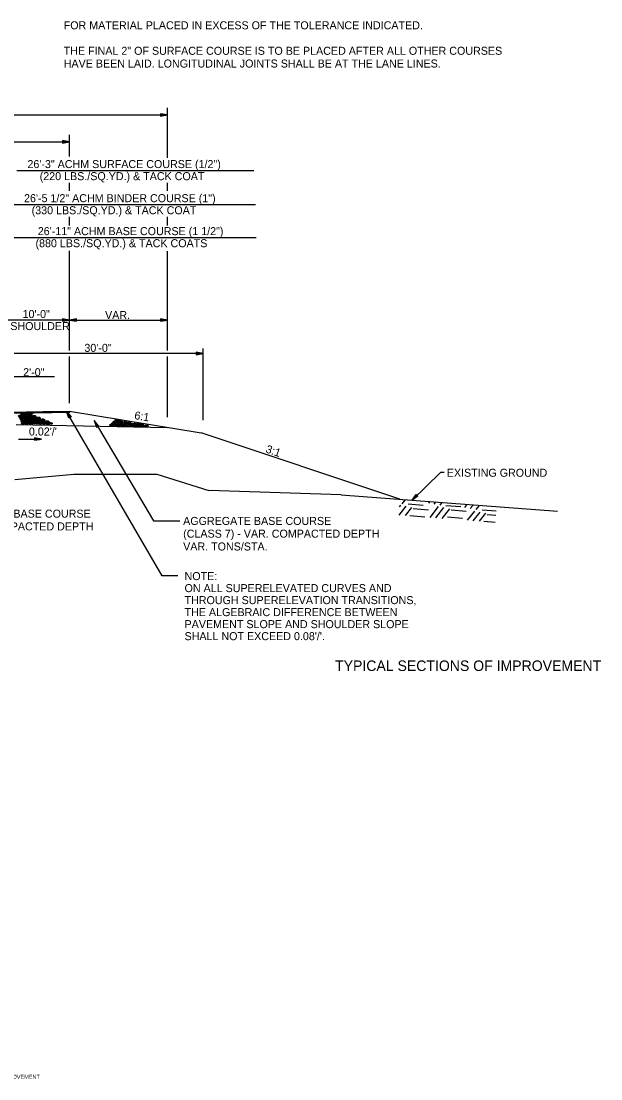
# Model space of a CAD drawing. Extents: x 1734743 to 1735935, y 759845 to 763831.
# Drawn here: x 1735827.7 to 1735914.7, y 762764.7 to 762923.3 of the extents above; entities that cross this region are included whole.
import ezdxf

# ---------------------------------------------------------------- set-up
doc = ezdxf.new("R2010")
doc.units = 0
for name, color, linetype in [('1', 7, 'Continuous'), ('10', 7, 'Continuous'), ('11', 7, 'Continuous'), ('19', 7, 'Continuous'), ('8', 7, 'Continuous'), ('9', 7, 'Continuous'), ('G-ANNO-TEXT', 7, 'Continuous'), ('Level 1', 7, 'Continuous'), ('R_Prop Surface', 7, 'Continuous')]:
    doc.layers.add(name, color=color, linetype=linetype)

# ---------------------------------------------------------------- blocks, each defined once
blk = doc.blocks.new('TM')
at = {"layer": '8'}
for p, q in [((-120.309, 21.181), (-119.787, -20.829)), ((0, 0), (-120.309, 21.181)), ((-31.382, 2.945), (-120.176, 10.512)), ((-119.787, -20.829), (0, 0)), ((-119.911, -10.826), (-31.307, -3.057))]:
    blk.add_line(p, q, dxfattribs=at)
blk = doc.blocks.new('ROCKS')
at = {"layer": '1'}
blk.add_spline([(0.013, 0.06), (0.053, 0.053), (0.107, 0.033), (0.133, 0.013), (0.133, -0.007), (0.12, -0.033), (0.107, -0.04), (0.073, -0.053), (0.033, -0.067), (0.013, -0.067), (-0.02, -0.06), (-0.06, -0.053), (-0.087, -0.047), (-0.113, -0.02), (-0.113, -0.007), (-0.107, 0.02), (-0.087, 0.033), (-0.067, 0.047), (-0.033, 0.053), (-0.02, 0.06), (0.013, 0.06)], degree=3, dxfattribs=at)

msp = doc.modelspace()

# ---------------------------------------------------------------- linework, layer by layer
at = {"layer": '11'}
for p, q in [((1735826.79, 762854.56), (1735835.65, 762855.39)), ((1735835.65, 762855.39), (1735848.06, 762855.39)), ((1735848.06, 762855.39), (1735855.89, 762852.91)), ((1735875.71, 762852.28), (1735855.89, 762852.91))]:
    msp.add_line(p, q, dxfattribs=at)
msp.add_lwpolyline([(1735875.71, 762852.28), (1735908.15, 762849.8)], dxfattribs=at)
at = {"layer": '19'}
for p, q in [((1735782.43, 762909.21), (1735849.62, 762909.21)), ((1735848.61, 762909.39), (1735848.61, 762909.03)), ((1735849.66, 762909.21), (1735848.61, 762909.39)), ((1735849.38, 762909.24), (1735848.61, 762909.3)), ((1735848.61, 762909.03), (1735849.66, 762909.21)), ((1735848.61, 762909.11), (1735849.38, 762909.18)), ((1735849.66, 762902.77), (1735849.66, 762910.26)), ((1735796.97, 762905.17), (1735834.97, 762905.17)), ((1735833.92, 762905.36), (1735833.92, 762904.99)), ((1735834.97, 762905.17), (1735833.92, 762905.36)), ((1735834.69, 762905.2), (1735833.92, 762905.26)), ((1735833.92, 762904.99), (1735834.97, 762905.17)), ((1735833.92, 762905.08), (1735834.69, 762905.15)), ((1735827.1, 762900.88), (1735862.63, 762900.88)), ((1735825.2, 762895.78), (1735862.86, 762895.78)), ((1735825.1, 762890.84), (1735862.96, 762890.84)), ((1735849.66, 762873.88), (1735849.66, 762888.81)), ((1735833.92, 762878.65), (1735833.92, 762878.28)), ((1735834.97, 762878.47), (1735833.92, 762878.65)), ((1735834.69, 762878.49), (1735833.92, 762878.56)), ((1735833.92, 762878.28), (1735834.97, 762878.47)), ((1735833.92, 762878.37), (1735834.69, 762878.44)), ((1735836.02, 762878.65), (1735834.97, 762878.47)), ((1735834.97, 762878.47), (1735836.02, 762878.28)), ((1735836.02, 762878.56), (1735835.25, 762878.49)), ((1735835.25, 762878.44), (1735836.02, 762878.37)), ((1735836.02, 762878.28), (1735836.02, 762878.65)), ((1735848.61, 762878.65), (1735848.61, 762878.28)), ((1735849.66, 762878.47), (1735848.61, 762878.65)), ((1735849.38, 762878.49), (1735848.61, 762878.56)), ((1735848.61, 762878.28), (1735849.66, 762878.47)), ((1735848.61, 762878.37), (1735849.38, 762878.44)), ((1735849.66, 762863.91), (1735849.66, 762873)), ((1735853.96, 762873.63), (1735853.96, 762873.26)), ((1735855.01, 762873.45), (1735853.96, 762873.63)), ((1735854.73, 762873.47), (1735853.96, 762873.53)), ((1735853.96, 762873.26), (1735855.01, 762873.45)), ((1735853.96, 762873.35), (1735854.73, 762873.42)), ((1735832.72, 762869.94), (1735824.97, 762869.94)), ((1735827, 762864.67), (1735834.97, 762864.83)), ((1735834.9, 762863.77), (1735834.53, 762864.77)), ((1735834.53, 762864.77), (1735835.22, 762863.95)), ((1735834.97, 762864.83), (1735854.71, 762861.54)), ((1735826.96, 762864.5), (1735835.05, 762864.66)), ((1735834.97, 762863.81), (1735834.64, 762864.51)), ((1735834.69, 762864.54), (1735835.13, 762863.91)), ((1735835.22, 762863.95), (1735834.9, 762863.77)), ((1735838.66, 762863.41), (1735847.59, 762848.36)), ((1735839.35, 762862.6), (1735838.66, 762863.41)), ((1735838.66, 762863.41), (1735839.04, 762862.42)), ((1735839.28, 762862.56), (1735838.83, 762863.19)), ((1735826.96, 762862.83), (1735849.66, 762862.38)), ((1735838.79, 762863.16), (1735839.12, 762862.47)), ((1735839.04, 762862.42), (1735839.35, 762862.6)), ((1735827.34, 762860.61), (1735830.76, 762860.61)), ((1735884.5, 762851.61), (1735854.71, 762861.54)), ((1735886.35, 762851.46), (1735886.98, 762852.33)), ((1735886.54, 762851.67), (1735887.04, 762852.26)), ((1735887.17, 762852.13), (1735886.57, 762851.64)), ((1735886.98, 762852.33), (1735887.23, 762852.07)), ((1735884.41, 762849.24), (1735885.44, 762850.55)), ((1735884.48, 762850.48), (1735884.66, 762850.7)), ((1735884.86, 762850.93), (1735885.3, 762851.48)), ((1735885.75, 762850.9), (1735888, 762850.7)), ((1735887.23, 762852.07), (1735886.35, 762851.46)), ((1735888.87, 762851.04), (1735888.98, 762851.19)), ((1735889.05, 762848.88), (1735890.33, 762850.5)), ((1735889.66, 762850.89), (1735889.84, 762851.12)), ((1735890.54, 762850.73), (1735890.79, 762851.05)), ((1735891.43, 762850.69), (1735893.68, 762850.5)), ((1735894.28, 762850.38), (1735894.58, 762850.75)), ((1735895.07, 762850.22), (1735895.44, 762850.69)), ((1735895.95, 762850.06), (1735896.39, 762850.61)), ((1735885.36, 762849.17), (1735886.32, 762850.39)), ((1735886.01, 762849.16), (1735888.26, 762848.97)), ((1735886.53, 762850.2), (1735888.79, 762850.01)), ((1735889.9, 762848.82), (1735891.12, 762850.35)), ((1735890.85, 762848.74), (1735892, 762850.18)), ((1735891.68, 762848.96), (1735893.93, 762848.77)), ((1735892.21, 762850), (1735894.46, 762849.81)), ((1735894.64, 762848.45), (1735895.75, 762849.84)), ((1735895.5, 762848.38), (1735896.54, 762849.68)), ((1735896.45, 762848.31), (1735897.42, 762849.52)), ((1735896.84, 762850.03), (1735898.94, 762849.85)), ((1735897.62, 762849.34), (1735898.89, 762849.23)), ((1735847.59, 762848.36), (1735851.5, 762848.36)), ((1735897.1, 762848.3), (1735898.81, 762848.15))]:
    msp.add_line(p, q, dxfattribs=at)
for points in [[(1735835.05, 762864.66), (1735827.05, 762864.5), (1735804.98, 762864.06), (1735800.88, 762863.98), (1735800.88, 762863.98), (1735796.88, 762863.9), (1735796.97, 762864.07), (1735796.97, 762864.07), (1735803.43, 762864.19), (1735830.97, 762864.75), (1735834.97, 762864.83), (1735834.97, 762864.83), (1735835.05, 762864.66), (1735835.05, 762864.66), (1735835.05, 762864.66)], [(1735891.18, 762855.64), (1735890.61, 762855.64), (1735886.35, 762851.46)]]:
    msp.add_lwpolyline(points, dxfattribs=at)
at = {"layer": '9'}
for p, q in [((1735834.97, 762902.98), (1735834.97, 762906.21)), ((1735834.97, 762897.82), (1735834.97, 762899.05)), ((1735849.66, 762897.82), (1735849.66, 762899.05)), ((1735834.97, 762892.62), (1735834.97, 762893.95)), ((1735849.66, 762892.62), (1735849.66, 762893.95)), ((1735834.97, 762879.38), (1735834.97, 762888.83)), ((1735834.97, 762873.88), (1735834.97, 762879.38)), ((1735834.97, 762878.47), (1735824.97, 762878.47)), ((1735834.97, 762878.47), (1735849.66, 762878.47)), ((1735855.01, 762873.45), (1735824.97, 762873.45)), ((1735834.97, 762867.93), (1735834.97, 762873)), ((1735855.01, 762863.45), (1735855.01, 762874.22)), ((1735834.97, 762866), (1735834.97, 762867.93)), ((1735848.85, 762840.14), (1735834.53, 762864.77))]:
    msp.add_line(p, q, dxfattribs=at)
msp.add_lwpolyline([(1735851.21, 762840.14), (1735848.85, 762840.14)], dxfattribs=at)
at = {"layer": 'R_Prop Surface'}
msp.add_line((1735834.97, 762864.83), (1735835.05, 762864.66), dxfattribs=at)

# ---------------------------------------------------------------- block references
at = {"layer": '19', "xscale": 0.008761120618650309, "yscale": 0.008761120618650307, "rotation": -0.7994241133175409}
msp.add_blockref('TM', (1735830.76, 762860.61), dxfattribs=at)
at = {"layer": 'Level 1'}
for p, xscale, yscale, rotation in [((1735827.6, 762864.07), 2.0116542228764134, -2.011654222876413, 177.9586193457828), ((1735827.75, 762863.81), 2.0116542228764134, -2.011654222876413, 177.9586193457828), ((1735827.89, 762863.56), 2.0116542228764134, -2.011654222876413, 177.9586193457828), ((1735828.01, 762864.35), 2.0116542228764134, -2.011654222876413, 177.9586193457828), ((1735828.02, 762863.29), 2.0116542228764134, -2.011654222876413, 177.9586193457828), ((1735828.13, 762864.08), 2.0116542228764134, -2.011654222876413, 177.9586193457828), ((1735828.29, 762863.82), 2.0116542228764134, -2.011654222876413, 177.9586193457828), ((1735828.44, 762863.55), 2.0116542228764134, -2.011654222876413, 177.9586193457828), ((1735828.56, 762863.29), 2.0116542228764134, -2.011654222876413, 177.9586193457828), ((1735828.59, 762864.38), 2.011654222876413, -2.0116542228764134, 177.95871721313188), ((1735828.67, 762864.12), 2.011654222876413, -2.0116542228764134, 177.95871721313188), ((1735828.82, 762863.85), 2.0116542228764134, -2.011654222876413, 177.9586193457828), ((1735828.96, 762863.59), 2.0116542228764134, -2.011654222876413, 177.9586193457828), ((1735829.09, 762863.31), 2.0116542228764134, -2.011654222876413, 177.9586193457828), ((1735829.09, 762863.04), 2.0116542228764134, -2.011654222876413, 177.9586193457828), ((1735829.11, 762864.34), 2.011654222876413, -2.0116542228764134, 177.95871721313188), ((1735829.2, 762864.07), 2.011654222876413, -2.0116542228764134, 177.95871721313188), ((1735829.33, 762863.81), 2.011654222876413, -2.0116542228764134, 177.95871721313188), ((1735829.46, 762863.56), 2.011654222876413, -2.0116542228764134, 177.95871721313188), ((1735829.58, 762863.3), 2.011654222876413, -2.0116542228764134, 177.95871721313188), ((1735829.7, 762864.05), 2.011654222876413, -2.0116542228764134, 177.95871721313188), ((1735829.84, 762863.8), 2.011654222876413, -2.0116542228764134, 177.95871721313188), ((1735829.97, 762863.55), 2.011654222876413, -2.0116542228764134, 177.95871721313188), ((1735830.09, 762863.3), 2.011654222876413, -2.0116542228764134, 177.95871721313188), ((1735830.35, 762863.8), 2.011654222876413, -2.0116542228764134, 177.95871721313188), ((1735830.49, 762863.54), 2.011654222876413, -2.0116542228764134, 177.95871721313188), ((1735830.62, 762863.27), 2.011654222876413, -2.0116542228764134, 177.95871721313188), ((1735831, 762863.52), 2.011654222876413, -2.0116542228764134, 177.95871721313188), ((1735831.13, 762863.27), 2.011654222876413, -2.0116542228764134, 177.95871721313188), ((1735831.66, 762863.25), 2.011654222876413, -2.0116542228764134, 177.95871721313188), ((1735841.78, 762863.21), 2.011654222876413, -2.011654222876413, 178.17361855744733), ((1735842.09, 762863.46), 2.011654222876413, -2.011654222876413, 178.17361855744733), ((1735842.29, 762863.2), 2.011654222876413, -2.011654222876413, 178.17361855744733), ((1735842.6, 762863.4), 2.011654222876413, -2.011654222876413, 178.17361855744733), ((1735842.8, 762863.16), 2.011654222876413, -2.011654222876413, 178.17361855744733), ((1735843.33, 762863.13), 2.011654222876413, -2.011654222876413, 178.17361855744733), ((1735843.89, 762863.09), 2.011654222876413, -2.011654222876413, 178.17361855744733), ((1735828.02, 762863), 2.0116542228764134, -2.011654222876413, 177.9586193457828), ((1735828.56, 762863.02), 2.0116542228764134, -2.011654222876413, 177.9586193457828), ((1735829.58, 762863.02), 2.011654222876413, -2.0116542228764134, 177.95871721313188), ((1735830.11, 762863.02), 2.011654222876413, -2.0116542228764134, 177.95871721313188), ((1735830.62, 762863), 2.011654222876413, -2.0116542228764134, 177.95871721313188), ((1735831.13, 762862.99), 2.011654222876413, -2.0116542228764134, 177.95871721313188), ((1735831.66, 762862.98), 2.011654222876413, -2.0116542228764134, 177.95871721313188), ((1735832.17, 762862.98), 2.011654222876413, -2.0116542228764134, 177.95871721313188), ((1735841.29, 762862.72), 2.011654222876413, -2.011654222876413, 178.17361855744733), ((1735841.56, 762862.96), 2.011654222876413, -2.011654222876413, 178.17361855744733), ((1735841.82, 762862.72), 2.011654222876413, -2.011654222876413, 178.17361855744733), ((1735842.06, 762862.97), 2.011654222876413, -2.011654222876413, 178.17361855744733), ((1735842.34, 762862.74), 2.011654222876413, -2.011654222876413, 178.17361855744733), ((1735842.59, 762862.95), 2.011654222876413, -2.011654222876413, 178.17361855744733), ((1735842.86, 762862.71), 2.011654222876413, -2.011654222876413, 178.17361855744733), ((1735843.11, 762862.92), 2.011654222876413, -2.011654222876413, 178.17361855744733), ((1735843.42, 762862.67), 2.011654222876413, -2.011654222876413, 178.17361855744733), ((1735843.67, 762862.87), 2.011654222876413, -2.011654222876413, 178.17361855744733), ((1735844.02, 762862.67), 2.011654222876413, -2.011654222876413, 178.17361855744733), ((1735844.28, 762862.87), 2.011654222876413, -2.011654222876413, 178.17361855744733), ((1735844.51, 762862.65), 2.011654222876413, -2.011654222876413, 178.17361855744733), ((1735844.77, 762862.87), 2.011654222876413, -2.011654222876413, 178.17361855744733), ((1735845.01, 762862.64), 2.011654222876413, -2.011654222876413, 178.17361855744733), ((1735845.28, 762862.87), 2.011654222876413, -2.011654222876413, 178.17361855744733), ((1735845.51, 762862.63), 2.011654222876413, -2.011654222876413, 178.17361855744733), ((1735845.8, 762862.86), 2.011654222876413, -2.011654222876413, 178.17361855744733), ((1735846.01, 762862.62), 2.011654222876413, -2.011654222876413, 178.17361855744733), ((1735846.53, 762862.61), 2.011654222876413, -2.011654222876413, 178.17361855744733)]:
    msp.add_blockref('ROCKS', p, dxfattribs=dict(at, xscale=xscale, yscale=yscale, rotation=rotation))

# ---------------------------------------------------------------- texts
at = {"layer": '1'}
for s, p in [('FOR MATERIAL PLACED IN EXCESS OF THE TOLERANCE INDICATED.', (1735834.11, 762922.04)), ('THE FINAL 2" OF SURFACE COURSE IS TO BE PLACED AFTER ALL OTHER COURSES', (1735834.11, 762918.22)), ('HAVE BEEN LAID. LONGITUDINAL JOINTS SHALL BE AT THE LANE LINES.', (1735834.11, 762916.31))]:
    msp.add_text(s, height=1.2, dxfattribs=at).set_placement(p)
at = {"layer": '10'}
for s, p in [('10\'-0"', (1735827.94, 762878.77)), ('VAR.', (1735840.31, 762878.62)), ('SHOULDER', (1735826.1, 762876.96)), ('30\'-0"', (1735837.21, 762873.7))]:
    msp.add_text(s, height=1.2, dxfattribs=at).set_placement(p)
for s, rotation, p in [('6:1', 350.5489, (1735844.64, 762863.63)), ('3:1', 340.4943, (1735864.3, 762858.66))]:
    msp.add_text(s, height=1.2, rotation=rotation, dxfattribs=at).set_placement(p)
at = {"layer": '19'}
for s, p in [('26\'-3" ACHM SURFACE COURSE (1/2")', (1735828.67, 762901.24)), ('(220 LBS./SQ.YD.) & TACK COAT', (1735830.51, 762899.43)), ('26\'-5 1/2" ACHM BINDER COURSE (1")', (1735828.16, 762896.13)), ('(330 LBS./SQ.YD.) & TACK COAT', (1735829.3, 762894.32)), ('26\'-11" ACHM BASE COURSE (1 1/2")', (1735830.22, 762891.19)), ('(880 LBS./SQ.YD.) & TACK COATS', (1735829.88, 762889.38)), ('2\'-0"', (1735828.03, 762870.05)), ("0.02'/'", (1735828.89, 762861.16)), ('EXISTING GROUND', (1735891.55, 762854.98)), ('26\'-0" AGGREGATE BASE COURSE', (1735811.42, 762848.85)), ('(CLASS 7) - 7" COMPACTED DEPTH', (1735811.42, 762846.94)), ('NOTE:', (1735852.23, 762839.49)), ('ON ALL SUPERELEVATED CURVES AND', (1735852.23, 762837.69)), ('THROUGH SUPERELEVATION TRANSITIONS,', (1735852.23, 762835.89)), ('THE ALGEBRAIC DIFFERENCE BETWEEN', (1735852.23, 762834.09)), ('PAVEMENT SLOPE AND SHOULDER SLOPE', (1735852.23, 762832.29)), ("SHALL NOT EXCEED 0.08'/'.", (1735852.23, 762830.49))]:
    msp.add_text(s, height=1.2, dxfattribs=at).set_placement(p)
for s, p in [('AGGREGATE BASE COURSE', (1735852.02, 762847.76)), ('(CLASS 7) - VAR. COMPACTED DEPTH', (1735852.02, 762845.85)), ('VAR. TONS/STA.', (1735852.02, 762843.93))]:
    msp.add_text(s, height=1.2, rotation=360, dxfattribs=at).set_placement(p)
at = {"layer": 'G-ANNO-TEXT'}
for height, p in [(1.575, (1735874.8, 762825.87)), (0.6, (1735814.83, 762764.75))]:
    msp.add_text('TYPICAL SECTIONS OF IMPROVEMENT', height=height, dxfattribs=at).set_placement(p)

doc.saveas('drawing.dxf')
